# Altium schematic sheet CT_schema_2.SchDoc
size 357 x 214 mm
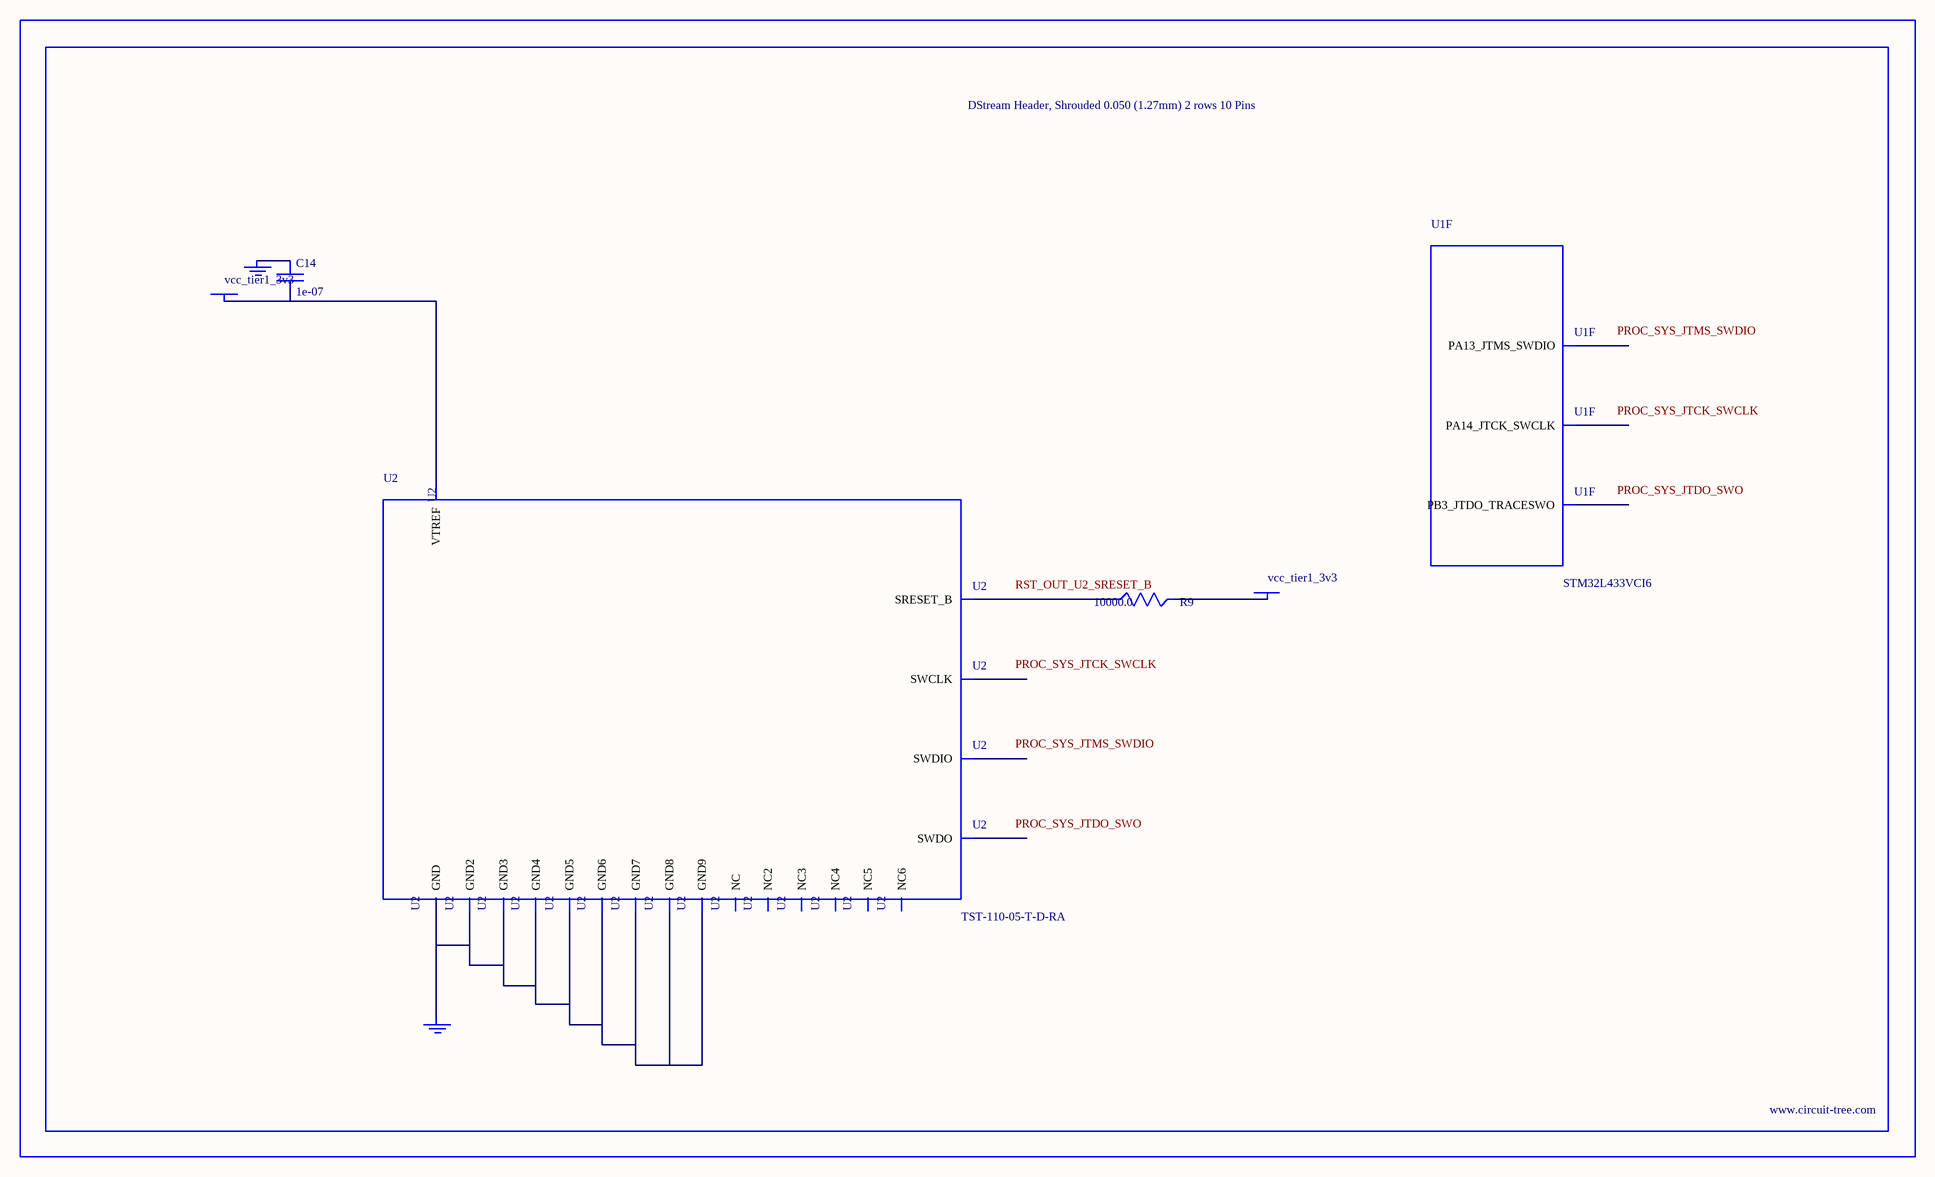
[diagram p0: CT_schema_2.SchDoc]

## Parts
BORDER1  (no value)
C14  1e-07  [C0402]
GND_INSTANCE_1_0  (no value)
GND_INSTANCE_1_1  (no value)
POWER_INSTANCE_1_0  vcc_tier1_3v3
POWER_INSTANCE_1_1  vcc_tier1_3v3
R9  10000.0  [R0603]
U1  STM32L433VCI6  [UFBGA100]  (part F of 11)
U2  TST-110-05-T-D-RA  [TST-110-05-T-D-RA]

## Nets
NetC14_1: C14.1 GND_INSTANCE_1_0.0(GND)
NetC14_2: C14.2 POWER_INSTANCE_1_0.0(PWR) U2.1(VTREF)
NetGND_INSTANCE_1_1_0: GND_INSTANCE_1_1.0(GND) U2.4(GND) U2.6(GND2) U2.8(GND3) U2.10(GND4) U2.12(GND5) U2.14(GND6) U2.16(GND7) U2.18(GND8) U2.20(GND9)
NetPOWER_INSTANCE_1_1_0: POWER_INSTANCE_1_1.0(PWR) R9.2
NetR9_1: R9.1 U2.15(SRESET_B)

Not connected (* = marked no-connect by the designer): U1 A8(PB3_JTDO_TRACESWO) A10(PA14_JTCK_SWCLK) A11(PA13_JTMS_SWDIO); U2 2(NC) 3(NC2) 5(NC3) 7(SWDIO) 9(SWCLK) 11(NC4) 13(SWDO) 17(NC5) 19(NC6)

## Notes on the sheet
- Labels drawn without touching a wire or pin: PROC_SYS_JTCK_SWCLK, PROC_SYS_JTDO_SWO, PROC_SYS_JTMS_SWDIO, RST_OUT_U2_SRESET_B

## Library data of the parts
BORDER1 = BORDER_PAGE1
C14 = C0402C104K3RACTU
GND_INSTANCE_1_0 GND_INSTANCE_1_1 = GND
POWER_INSTANCE_1_0 POWER_INSTANCE_1_1 = PWR
R9 = RC0603JR-0710KL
